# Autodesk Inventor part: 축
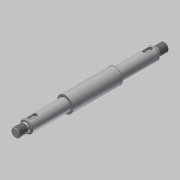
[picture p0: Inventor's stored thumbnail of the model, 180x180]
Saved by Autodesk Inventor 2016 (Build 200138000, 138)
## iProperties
Created: 2018-11
Part Number: 축
Material: 강철, 연강
Document SubType Name: Modeling
Designer: mduedu
Density: 1 g/cm^3
Appearance: 강철
Author: mduedu
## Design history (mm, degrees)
sketch "스케치1"
  geometry: L1 (-35, 0)-(35, 0); L2 (35, 0)-(35, 11); L3 (35, 11)-(-35, 11); L4 (-35, 11)-(-35, 0); L5 (-35, 0)-(-90, 0); L6 (-90, 0)-(-90, 8.5); L7 (-90, 8.5)-(-35, 8.5); L8 (-35, 8.5)-(-35, 0); L9 (-90, 0)-(-105, 0); L10 (-105, 0)-(-105, 6); L11 (-105, 6)-(-90, 6); L12 (-90, 6)-(-90, 0); L13 (0, 0)-(0, 11); L14 (35, 0)-(90, 0); L15 (90, 0)-(90, 8.5); L16 (90, 8.5)-(35, 8.5); L17 (35, 8.5)-(35, 0); L18 (90, 0)-(105, 0); L19 (105, 0)-(105, 6); L20 (105, 6)-(90, 6); L21 (90, 6)-(90, 0); 1 further point
  constraints: 42 end point, 6 parallel, 6 symmetric about line, 3 horizontal, 3 perpendicular, 2 midpoint, 1 coincident
  dimensions: "d0" = 22 diameter of L3 L1; "d2" = 17 diameter of L7 L5; "d3" = 12 diameter of L11 L9; "d4" = 70 distance of L2.end L3.end; "d5" = 55 distance of L6.end L7.end; "d6" = 210 distance between parallel lines of L19 L10
revolve "회전1" sketch "스케치1" stored, may be unused: angle "d7" = 90 deg
fillet "모깎기1" dims "d8" = 0.3
node "작업 평면1"
sketch "스케치2" dims "d11" = 12
  geometry: L1 (15, 2.5)-(22, 2.5); L2 (22, 2.5)-(22, -2.5); L3 (22, -2.5)-(15, -2.5); L4 (15, -2.5)-(15, 2.5); L5 (27.5, 8.5)-(27.5, -8.5) reference; 3 further points
  constraints: 8 end point, 2 midpoint, 2 parallel, 2 vertical alignment, 1 horizontal, 1 horizontal alignment, 1 perpendicular, 4 other
  dimensions: "d9" = 3 dimension on L5; "d10" = 5 distance between parallel lines of L3 L1
extrude "돌출1" cut sketch "스케치2" distance "d12" = 3; taper "d13" = 0 deg
chamfer "모따기1" distance "d14" = 1; stored, may be unused: second distance "d15" = 2, angle "d16" = 45 deg
feature "스레드1" dims "d17" = 12, "d18" = 0
feature "스레드2" dims "d19" = 12, "d20" = 0
chamfer "모따기2" distance "d21" = 1; stored, may be unused: second distance "d22" = 2, angle "d23" = 45 deg
node "솔리드1"
mirror "대칭1"
